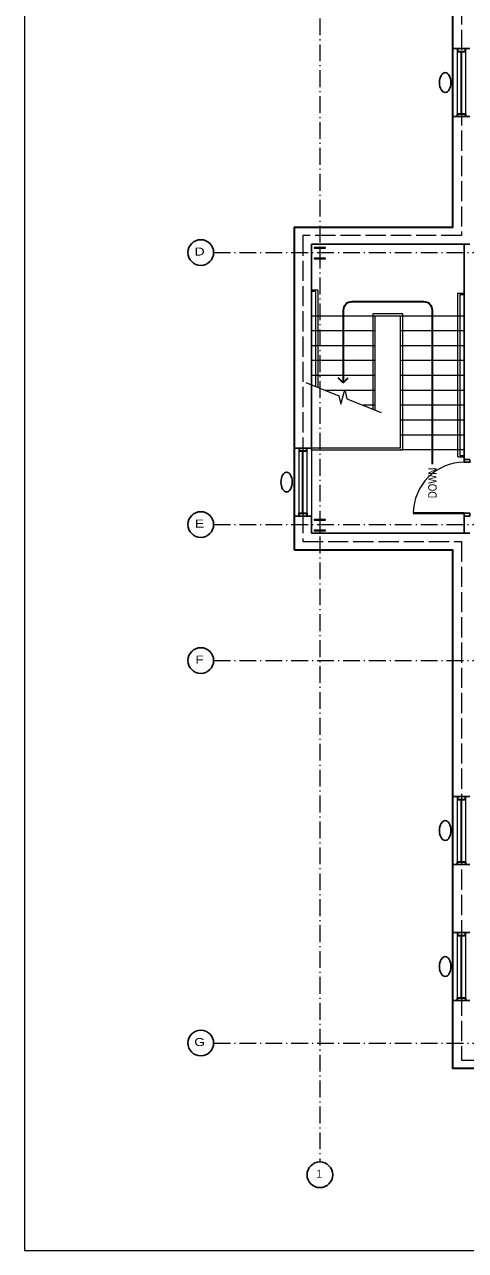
# Model space of a CAD drawing. Extents: x -118748 to -117136, y -118748 to -117596.
# Drawn here: x -118748 to -118499, y -118748 to -118056 of the extents above; entities that cross this region are included whole.
import ezdxf
from ezdxf.enums import TextEntityAlignment as Align

# ---------------------------------------------------------------- set-up
doc = ezdxf.new("R2010")
doc.units = 0
doc.header["$LTSCALE"] = 1.9
for name, pattern in [('DOT_DASHED', [7.7, 5, -1.2, 0.3, -1.2]), ('LONG_DASHED', [7.5, 6, -1.5]), ('MEDIUM_DASHED', [4.5, 3, -1.5])]:
    doc.linetypes.add(name, pattern=pattern)
for name, color, linetype, lineweight in [('10', 7, 'DOT_DASHED', 13), ('11', 7, 'Continuous', 25), ('12', 7, 'Continuous', 13), ('15', 7, 'Continuous', 13), ('16', 7, 'Continuous', 13), ('2', 7, 'Continuous', 35), ('20', 7, 'MEDIUM_DASHED', 13), ('23', 7, 'Continuous', 25), ('25', 7, 'Continuous', 13), ('26', 7, 'Continuous', 25), ('3', 7, 'Continuous', 35), ('40', 7, 'Continuous', 35), ('43', 7, 'Continuous', 25), ('46', 7, 'Continuous', 35), ('60', 7, 'LONG_DASHED', 13)]:
    doc.layers.add(name, color=color, linetype=linetype, lineweight=lineweight)

msp = doc.modelspace()

# ---------------------------------------------------------------- linework, layer by layer
at = {"layer": '10'}
for p, q in [((-118581.521, -117628.339), (-118581.521, -118698.41)), ((-118641.571, -118184.81), (-117285.521, -118184.81)), ((-118641.571, -118338.41), (-117285.521, -118338.41)), ((-118641.571, -118415.21), (-117285.521, -118415.21)), ((-118641.571, -118631.21), (-117285.521, -118631.21))]:
    msp.add_line(p, q, dxfattribs=at)
at = {"layer": '11'}
for centre in [(-118648.771, -118184.81), (-118648.771, -118338.41), (-118648.771, -118415.21), (-118648.771, -118631.21), (-118581.521, -118705.61)]:
    msp.add_circle(centre, 7.253, dxfattribs=at)
at = {"layer": '12'}
for points in [[(-118584.704, -118188.362), (-118578.288, -118188.362), (-118578.288, -118187.966), (-118581.372, -118187.966), (-118581.372, -118182.262), (-118578.288, -118182.262), (-118578.288, -118181.866), (-118584.704, -118181.866), (-118584.704, -118182.262), (-118581.62, -118182.262), (-118581.62, -118187.966), (-118584.704, -118187.966)], [(-118584.704, -118341.962), (-118578.288, -118341.962), (-118578.288, -118341.566), (-118581.372, -118341.566), (-118581.372, -118335.862), (-118578.288, -118335.862), (-118578.288, -118335.466), (-118584.704, -118335.466), (-118584.704, -118335.862), (-118581.62, -118335.862), (-118581.62, -118341.566), (-118584.704, -118341.566)]]:
    msp.add_lwpolyline(points, close=True, dxfattribs=at)
at = {"layer": '15', "lineweight": 25}
for p, q in [((-118506.321, -118031.21), (-118506.321, -118069.61)), ((-118496.721, -118069.61), (-118506.321, -118069.61)), ((-118496.721, -118108.01), (-118506.321, -118108.01)), ((-118506.321, -118108.01), (-118506.321, -118170.41)), ((-118506.321, -118170.41), (-118595.921, -118170.41)), ((-118595.921, -118170.41), (-118595.921, -118295.21)), ((-118496.721, -118180.01), (-118586.321, -118180.01)), ((-118586.321, -118180.01), (-118586.321, -118295.21)), ((-118586.321, -118295.21), (-118595.921, -118295.21)), ((-118586.321, -118333.61), (-118595.921, -118333.61)), ((-118595.921, -118333.61), (-118595.921, -118352.81)), ((-118586.321, -118333.61), (-118586.321, -118343.21)), ((-118586.321, -118343.21), (-118496.721, -118343.21)), ((-118595.921, -118352.81), (-118506.321, -118352.81)), ((-118506.321, -118352.81), (-118506.321, -118492.01)), ((-118496.721, -118492.01), (-118506.321, -118492.01)), ((-118496.721, -118530.41), (-118506.321, -118530.41)), ((-118506.321, -118530.41), (-118506.321, -118568.81)), ((-118496.721, -118568.81), (-118506.321, -118568.81)), ((-118496.721, -118607.21), (-118506.321, -118607.21)), ((-118506.321, -118607.21), (-118506.321, -118645.61)), ((-118506.321, -118645.61), (-118261.521, -118645.61))]:
    msp.add_line(p, q, dxfattribs=at)
at = {"layer": '16'}
for p, q in [((-118506.321, -118108.01), (-118506.321, -118069.61)), ((-118503.703, -118106.41), (-118503.703, -118071.21)), ((-118499.339, -118071.21), (-118499.339, -118106.41)), ((-118595.921, -118333.61), (-118595.921, -118295.21)), ((-118593.303, -118332.01), (-118593.303, -118296.81)), ((-118588.939, -118296.81), (-118588.939, -118332.01)), ((-118586.321, -118295.21), (-118586.321, -118333.61)), ((-118506.321, -118530.41), (-118506.321, -118492.01)), ((-118503.703, -118528.81), (-118503.703, -118493.61)), ((-118499.339, -118493.61), (-118499.339, -118528.81)), ((-118506.321, -118607.21), (-118506.321, -118568.81)), ((-118503.703, -118605.61), (-118503.703, -118570.41)), ((-118499.339, -118570.41), (-118499.339, -118605.61))]:
    msp.add_line(p, q, dxfattribs=at)
at = {"layer": '16', "lineweight": 35}
for p, q in [((-118501.521, -118106.41), (-118501.521, -118071.21)), ((-118591.121, -118332.01), (-118591.121, -118296.81)), ((-118501.521, -118528.81), (-118501.521, -118493.61)), ((-118501.521, -118605.61), (-118501.521, -118570.41))]:
    msp.add_line(p, q, dxfattribs=at)
for points in [[(-118503.703, -118069.61), (-118503.703, -118071.21), (-118499.339, -118071.21), (-118499.339, -118069.61)], [(-118503.703, -118108.01), (-118503.703, -118106.41), (-118499.339, -118106.41), (-118499.339, -118108.01)], [(-118593.303, -118295.21), (-118593.303, -118296.81), (-118588.939, -118296.81), (-118588.939, -118295.21)], [(-118593.303, -118333.61), (-118593.303, -118332.01), (-118588.939, -118332.01), (-118588.939, -118333.61)], [(-118503.703, -118492.01), (-118503.703, -118493.61), (-118499.339, -118493.61), (-118499.339, -118492.01)], [(-118503.703, -118530.41), (-118503.703, -118528.81), (-118499.339, -118528.81), (-118499.339, -118530.41)], [(-118503.703, -118568.81), (-118503.703, -118570.41), (-118499.339, -118570.41), (-118499.339, -118568.81)], [(-118503.703, -118607.21), (-118503.703, -118605.61), (-118499.339, -118605.61), (-118499.339, -118607.21)]]:
    msp.add_lwpolyline(points, dxfattribs=at)
at = {"layer": '2', "lineweight": 13}
msp.add_lwpolyline([(-118748.365, -118748.365), (-117365.965, -118748.365), (-117365.965, -117826.765), (-118748.365, -117826.765), (-118748.365, -118748.365), (-117135.565, -118748.365), (-117135.565, -117596.365), (-118748.365, -117596.365)], close=True, dxfattribs=at)
at = {"layer": '20', "linetype": 'Continuous'}
for p, q in [((-118499.921, -118180.01), (-118586.321, -118180.01)), ((-118586.321, -118259.511), (-118586.321, -118180.01)), ((-118499.921, -118296.25), (-118499.921, -118180.01)), ((-118582.721, -118206.094), (-118586.321, -118206.094)), ((-118583.921, -118206.874), (-118586.321, -118206.874)), ((-118583.921, -118206.874), (-118583.921, -118260.456)), ((-118582.721, -118206.094), (-118582.721, -118260.929)), ((-118503.521, -118300.244), (-118503.521, -118207.816)), ((-118503.521, -118207.816), (-118499.921, -118207.816)), ((-118502.321, -118299.474), (-118502.321, -118208.587)), ((-118502.321, -118208.587), (-118499.921, -118208.587)), ((-118550.321, -118220.65), (-118586.321, -118220.65)), ((-118535.921, -118220.65), (-118550.321, -118220.65)), ((-118550.321, -118273.693), (-118550.321, -118220.65)), ((-118535.921, -118295.05), (-118535.921, -118220.65)), ((-118499.921, -118220.65), (-118535.921, -118220.65)), ((-118550.321, -118229.05), (-118586.321, -118229.05)), ((-118499.921, -118229.05), (-118535.921, -118229.05)), ((-118550.321, -118237.45), (-118586.321, -118237.45)), ((-118499.921, -118237.45), (-118535.921, -118237.45)), ((-118550.321, -118245.85), (-118586.321, -118245.85)), ((-118499.921, -118245.85), (-118535.921, -118245.85)), ((-118550.321, -118254.25), (-118586.321, -118254.25)), ((-118499.921, -118254.25), (-118535.921, -118254.25)), ((-118567.401, -118262.65), (-118578.352, -118262.65)), ((-118550.321, -118262.65), (-118567.271, -118262.65)), ((-118499.921, -118262.65), (-118535.921, -118262.65)), ((-118586.321, -118296.25), (-118586.321, -118267.249)), ((-118550.321, -118271.05), (-118557.029, -118271.05)), ((-118499.921, -118271.05), (-118535.921, -118271.05)), ((-118499.921, -118279.45), (-118535.921, -118279.45)), ((-118499.921, -118287.85), (-118535.921, -118287.85)), ((-118586.321, -118295.05), (-118535.921, -118295.05)), ((-118586.321, -118296.25), (-118534.721, -118296.25)), ((-118499.921, -118296.25), (-118535.921, -118296.25)), ((-118502.321, -118299.474), (-118499.921, -118299.474)), ((-118503.521, -118300.244), (-118499.921, -118300.244))]:
    msp.add_line(p, q, dxfattribs=at)
for points in [[(-118534.721, -118296.25), (-118534.721, -118219.45), (-118551.521, -118219.45), (-118551.521, -118273.22)], [(-118589.523, -118258.25), (-118570.731, -118265.652), (-118569.721, -118270.476), (-118567.324, -118262.392), (-118566.292, -118267.401), (-118546.893, -118275.043)]]:
    msp.add_lwpolyline(points, dxfattribs=at)
at = {"layer": '23'}
for p, q in [((-118496.721, -118180.01), (-118499.921, -118180.01)), ((-118499.921, -118180.01), (-118499.921, -118301.61)), ((-118499.921, -118301.61), (-118496.721, -118301.61)), ((-118499.921, -118333.61), (-118496.721, -118333.61)), ((-118499.921, -118333.61), (-118499.921, -118343.21)), ((-118496.721, -118343.21), (-118499.921, -118343.21))]:
    msp.add_line(p, q, dxfattribs=at)
at = {"layer": '25', "lineweight": 40}
msp.add_line((-118528.721, -118332.01), (-118499.921, -118332.01), dxfattribs=at)
at = {"layer": '25'}
msp.add_arc((-118499.921, -118332.01), 28.8, 90.00001, 180, dxfattribs=at)
at = {"layer": '26'}
for points in [[(-118496.721, -118301.61), (-118496.721, -118303.21), (-118499.921, -118303.21), (-118499.921, -118301.61)], [(-118499.921, -118333.61), (-118499.921, -118332.01), (-118496.721, -118332.01), (-118496.721, -118333.61)]]:
    msp.add_lwpolyline(points, dxfattribs=at)
at = {"layer": '3'}
for points in [[(-118595.921, -118352.81), (-118595.921, -118170.41), (-118506.321, -118170.41), (-118506.321, -117954.41), (-118098.321, -117954.41), (-117829.521, -117954.41)], [(-117890.316, -118553.433), (-118075.926, -118553.433), (-118077.534, -118553.433), (-118077.559, -118555.032), (-118079.538, -118565.426), (-118080.102, -118566.923), (-118085.022, -118576.169), (-118086.007, -118577.43), (-118093.457, -118584.791), (-118094.773, -118585.701), (-118104.079, -118590.508), (-118105.606, -118590.985), (-118115.921, -118592.801), (-118119.121, -118592.81), (-118261.521, -118592.81), (-118261.521, -118645.61), (-118506.321, -118645.61), (-118506.321, -118352.81), (-118595.921, -118352.81)]]:
    msp.add_lwpolyline(points, dxfattribs=at)
at = {"layer": '40'}
for p, q in [((-118522.721, -118212.65), (-118563.521, -118212.65)), ((-118568.321, -118217.45), (-118568.321, -118258.45)), ((-118517.921, -118304.25), (-118517.921, -118217.45))]:
    msp.add_line(p, q, dxfattribs=at)
for centre, start, end in [((-118563.521, -118217.45), 90, 180), ((-118522.721, -118217.45), 0, 90)]:
    msp.add_arc(centre, 4.8, start, end, dxfattribs=at)
at = {"layer": '43'}
for centre in [(-118510.721, -118088.81), (-118600.321, -118314.41), (-118510.721, -118511.21), (-118510.721, -118588.01)]:
    msp.add_ellipse(centre, major_axis=(0, -5.6), ratio=0.571429, dxfattribs=at)
at = {"layer": '46'}
for q in [(-118571.149, -118255.622), (-118565.492, -118255.622)]:
    msp.add_line((-118568.321, -118258.45), q, dxfattribs=at)
at = {"layer": '60'}
for points in [[(-118501.521, -117959.21), (-118501.521, -118175.21), (-118591.121, -118175.21)], [(-118591.121, -118175.21), (-118591.121, -118348.01), (-118501.521, -118348.01)], [(-118501.521, -118348.01), (-118501.521, -118640.81), (-118266.321, -118640.81)]]:
    msp.add_lwpolyline(points, dxfattribs=at)

# ---------------------------------------------------------------- texts
at = {"layer": '11', "width": 1.3}
for s, p in [(' D ', (-118649.451, -118186.51)), (' E ', (-118649.451, -118340.11)), (' F ', (-118649.451, -118416.91)), (' G ', (-118649.451, -118632.91))]:
    msp.add_text(s, height=4.518, dxfattribs=at).set_placement(p, align=Align.CENTER)
at = {"layer": '11'}
msp.add_text(' 1 ', height=4.518, dxfattribs=at).set_placement((-118581.934, -118707.31), align=Align.CENTER)
at = {"layer": '46', "width": 0.85}
msp.add_text('DOWN', height=4.8, rotation=90, dxfattribs=at).set_placement((-118515.521, -118306.288), align=Align.RIGHT)

doc.saveas('drawing.dxf')
